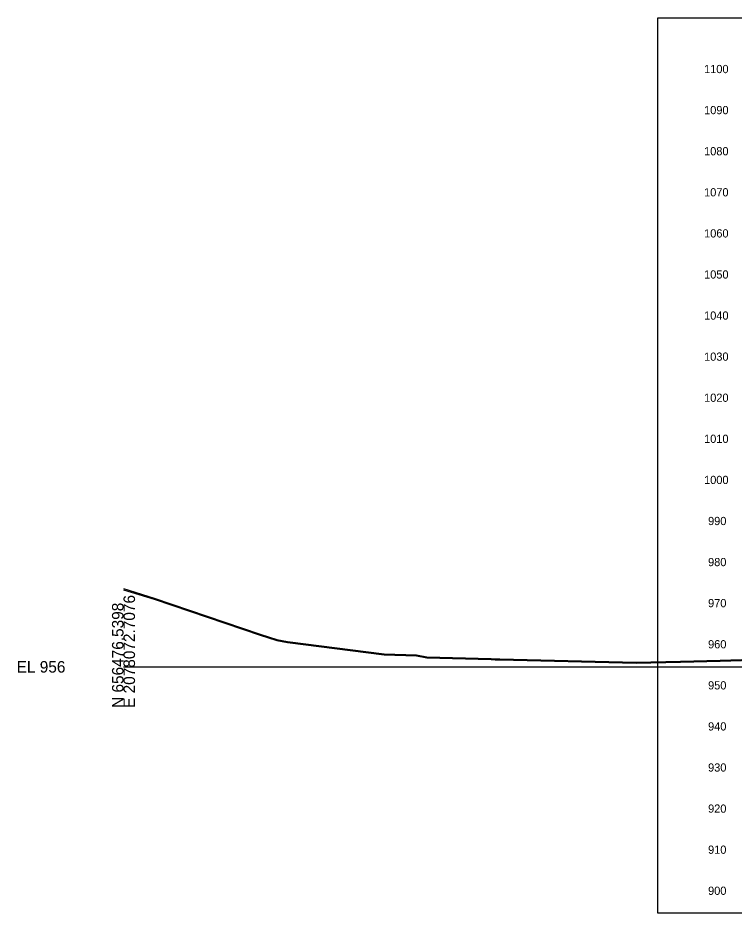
# Model space of a CAD drawing. Extents: x 5868 to 6683, y 2883 to 19120.
# Drawn here: x 5868.1 to 6042.3, y 15385.1 to 15603 of the extents above; entities that cross this region are included whole.
import ezdxf

# ---------------------------------------------------------------- set-up
doc = ezdxf.new("R2010")
doc.units = 0
for name, color, linetype in [('DESIGN - SHEET - Corner Text', 7, 'Continuous'), ('DESIGN - SHEET - Light Grid', 7, 'Continuous'), ('DESIGN - SHEET - Plot Shape', 7, 'Continuous'), ('SURVEY - GROUND - Bottom of Topsoil Layer', 7, 'Continuous'), ('SURVEY - GROUND - Top of Ground', 7, 'Continuous')]:
    doc.layers.add(name, color=color, linetype=linetype)

msp = doc.modelspace()

# ---------------------------------------------------------------- linework, layer by layer
at = {"layer": 'DESIGN - SHEET - Light Grid'}
msp.add_line((5893.78, 15445.07), (6193.78, 15445.07), dxfattribs=at)
at = {"layer": 'DESIGN - SHEET - Plot Shape'}
msp.add_lwpolyline([(6023.78, 15603.01), (6363.78, 15603.01), (6363.78, 15385.13), (6023.78, 15385.13)], close=True, dxfattribs=at)
at = {"layer": 'SURVEY - GROUND - Bottom of Topsoil Layer'}
msp.add_lwpolyline([(5893.78, 15463.85), (5901.21, 15461.57), (5927, 15452.76), (5931.08, 15451.47), (5933.7, 15451), (5957.18, 15448.02), (5965.09, 15447.73), (5967.54, 15447.29), (5983.26, 15446.84), (5984.21, 15446.8), (5985.37, 15446.76), (6018.52, 15445.94), (6029.32, 15446.2), (6038.97, 15446.43), (6059.85, 15447.07)], dxfattribs=at)
at = {"layer": 'SURVEY - GROUND - Top of Ground'}
msp.add_lwpolyline([(5893.78, 15464.1), (5901.21, 15461.82), (5927, 15453.01), (5931.08, 15451.72), (5933.7, 15451.25), (5957.18, 15448.27), (5965.09, 15447.98), (5967.54, 15447.54), (5983.26, 15447.09), (5984.21, 15447.05), (5985.37, 15447.01), (6018.52, 15446.19), (6029.32, 15446.45), (6038.97, 15446.68), (6059.85, 15447.32)], dxfattribs=at)

# ---------------------------------------------------------------- texts
at = {"layer": 'DESIGN - SHEET - Corner Text'}
for s, p in [('1100', (6035.03, 15589.57)), ('1090', (6035.03, 15579.57)), ('1080', (6035.03, 15569.57)), ('1070', (6035.03, 15559.57)), ('1060', (6035.03, 15549.57)), ('1050', (6035.03, 15539.57)), ('1040', (6035.03, 15529.57)), ('1030', (6035.03, 15519.57)), ('1020', (6035.03, 15509.57)), ('1010', (6035.03, 15499.57)), ('1000', (6035.03, 15489.57)), ('990', (6036, 15479.57)), ('980', (6036, 15469.57)), ('970', (6036, 15459.57)), ('960', (6036, 15449.57)), ('950', (6036, 15439.57)), ('940', (6036, 15429.57)), ('930', (6036, 15419.57)), ('920', (6036, 15409.57)), ('910', (6036, 15399.57)), ('900', (6036, 15389.57))]:
    msp.add_text(s, height=2, dxfattribs=at).set_placement(p)
at = {"layer": 'DESIGN - SHEET - Light Grid'}
for s, p in [('E 2078072.7076', (5896.58, 15435.07)), ('N 656476.5398', (5893.78, 15435.07))]:
    msp.add_text(s, height=2.8, rotation=90, dxfattribs=at).set_placement(p)
msp.add_text('EL 956', height=2.8, dxfattribs=at).set_placement((5867.78, 15443.67))

doc.saveas('drawing.dxf')
